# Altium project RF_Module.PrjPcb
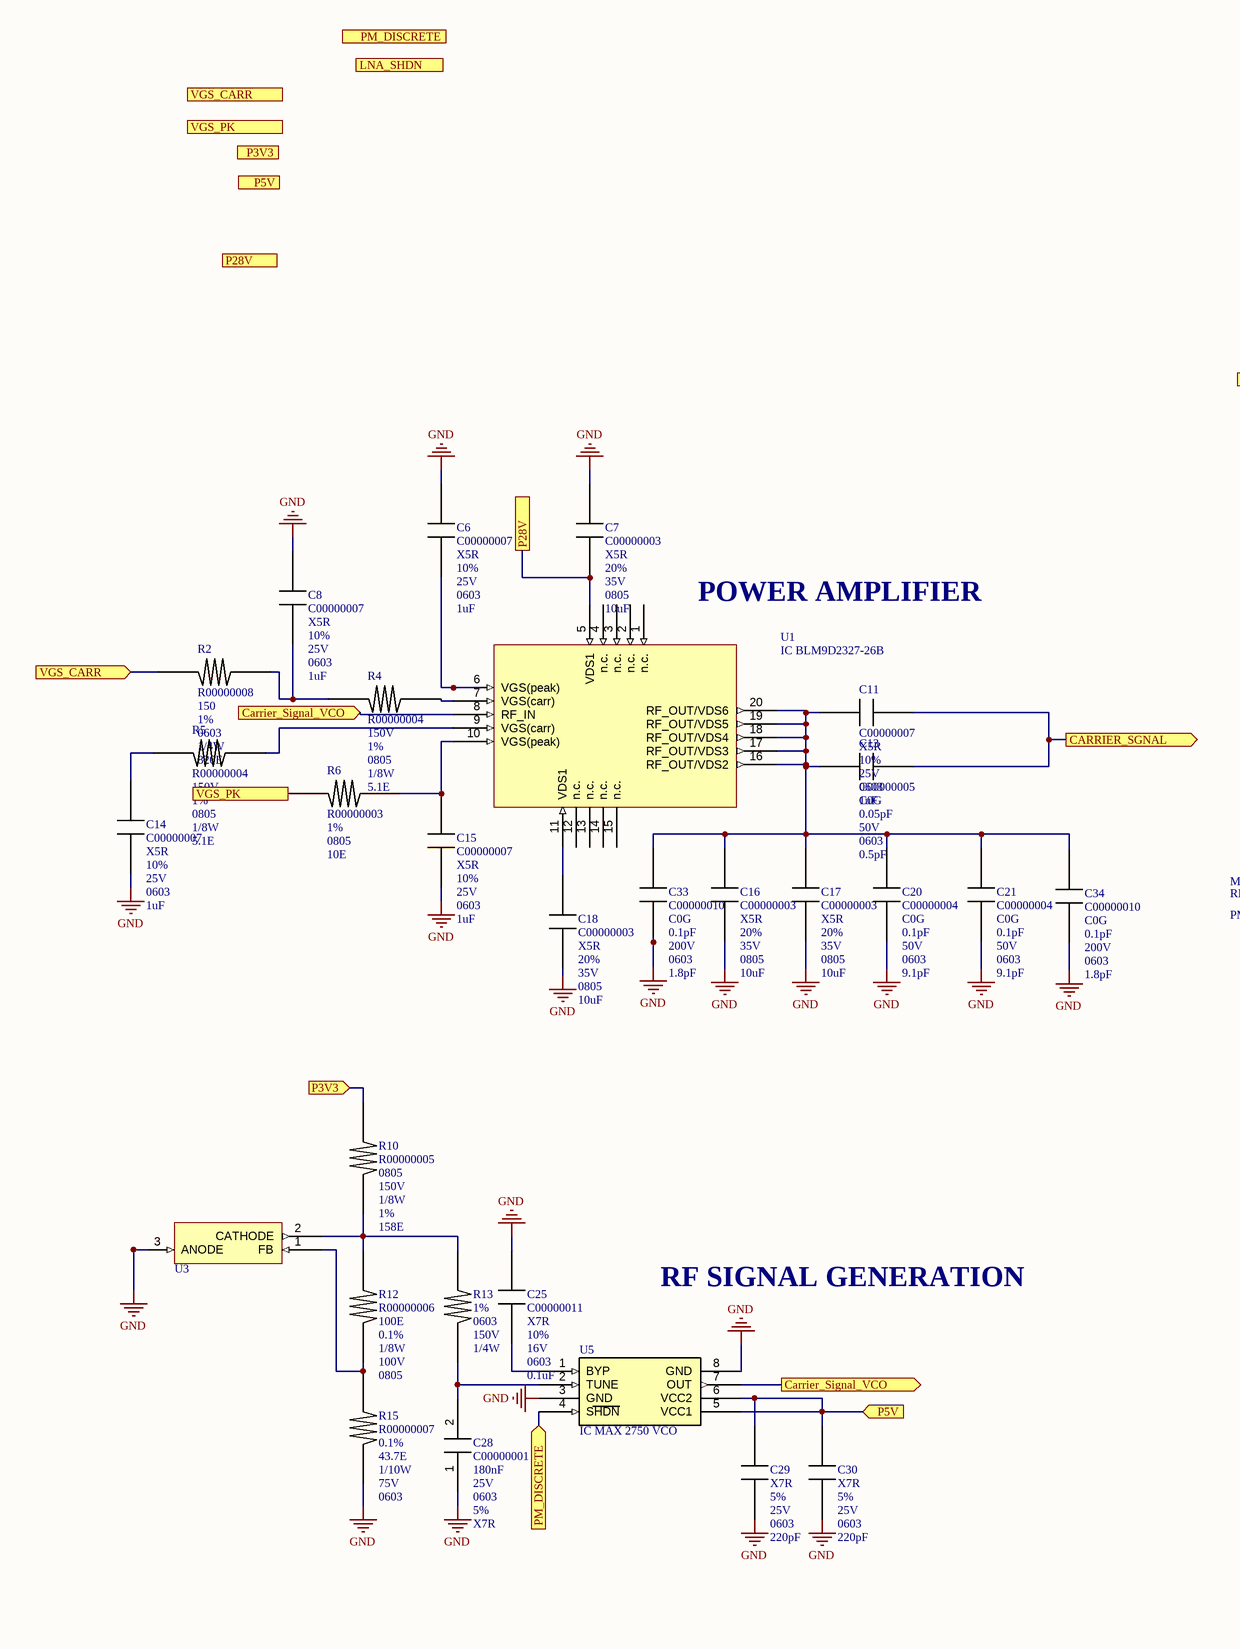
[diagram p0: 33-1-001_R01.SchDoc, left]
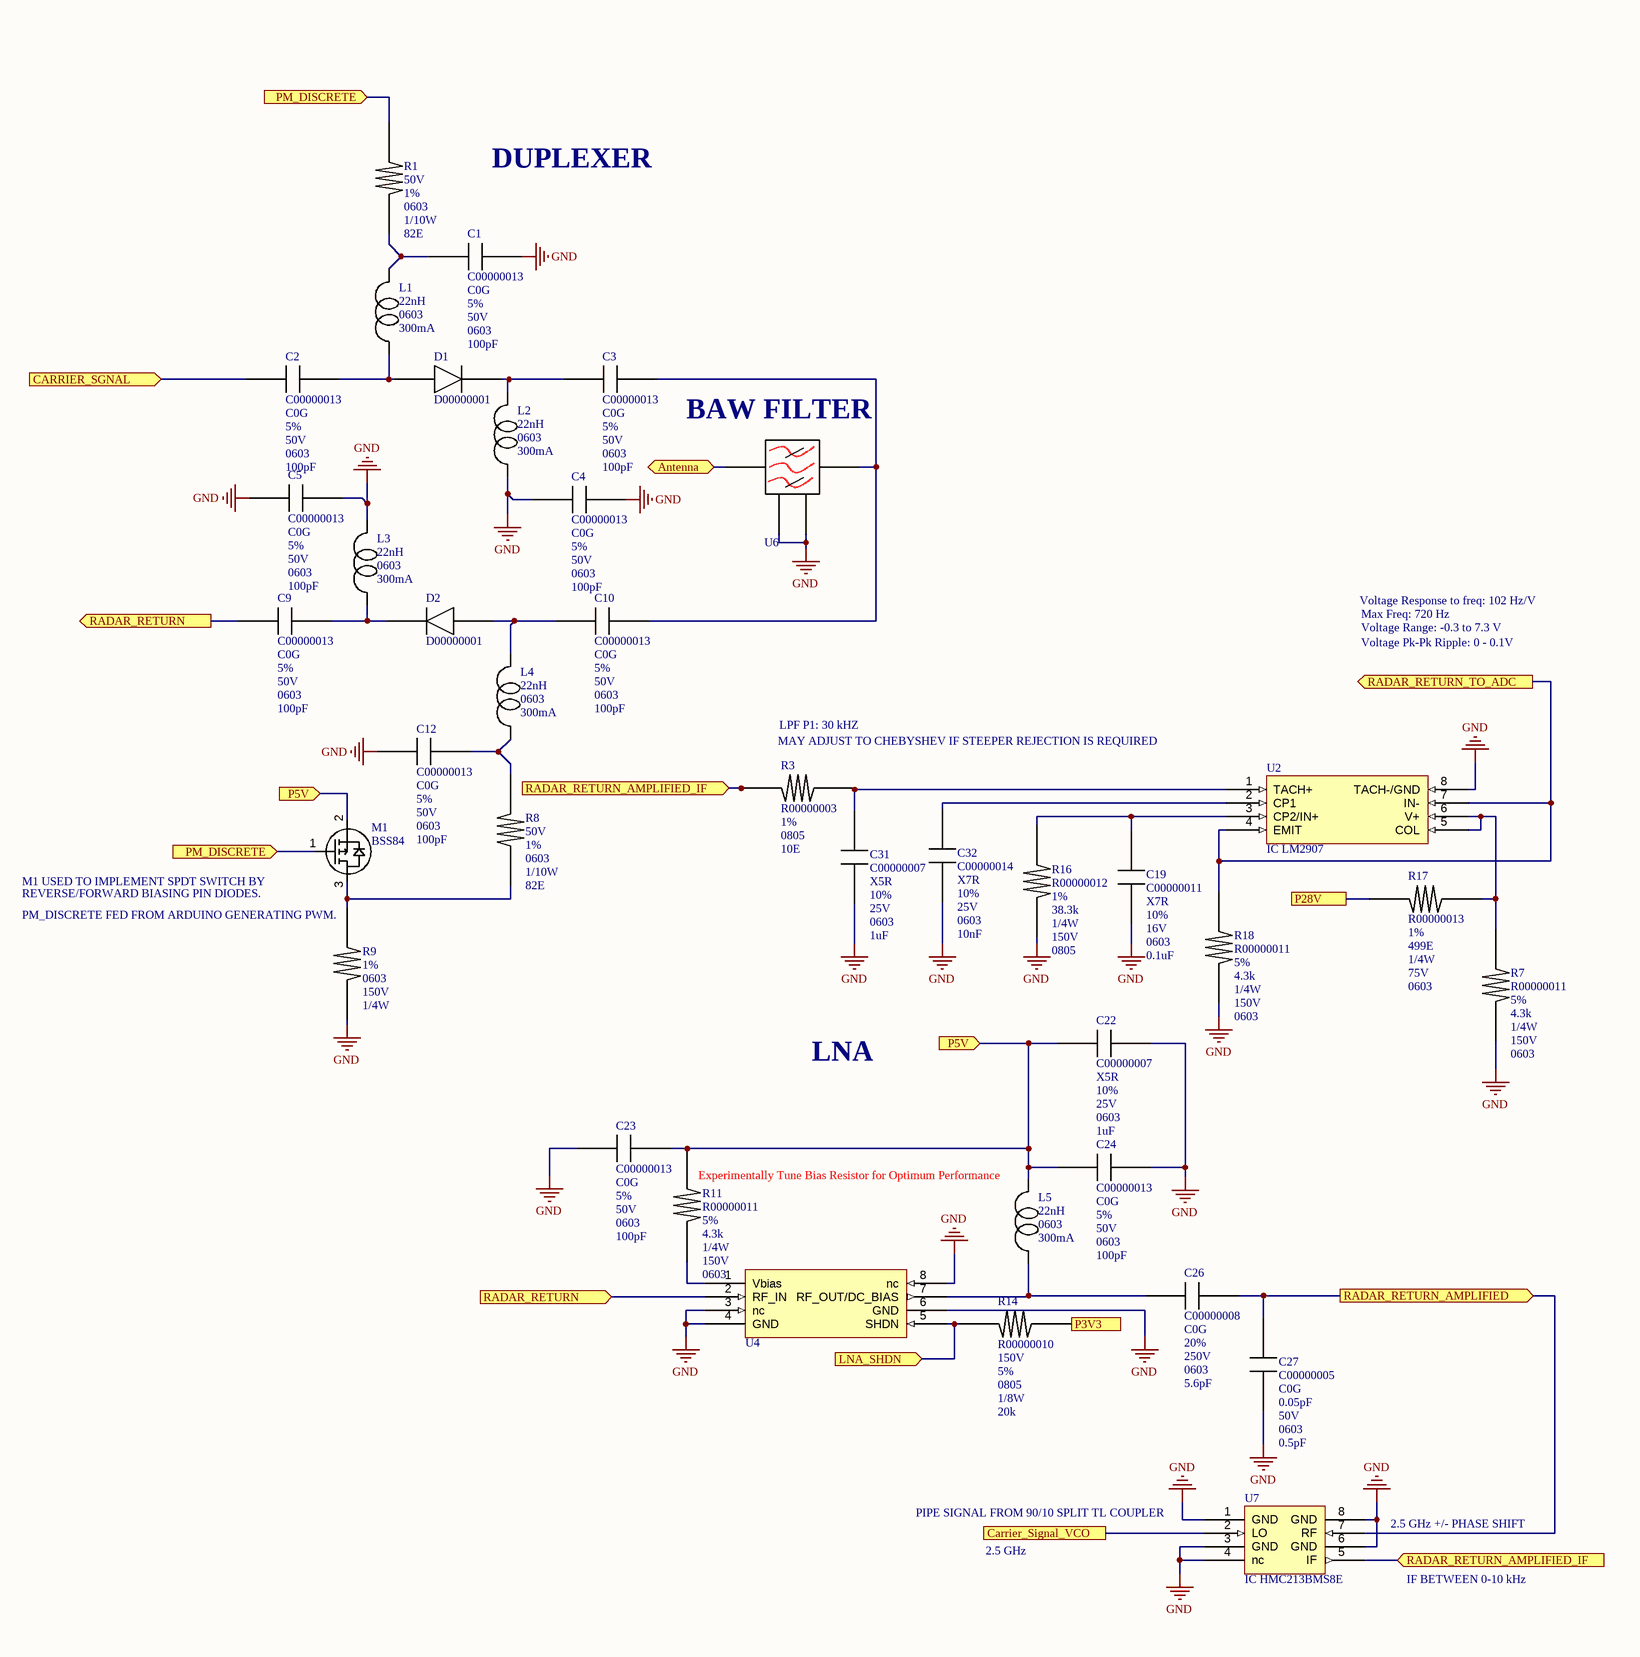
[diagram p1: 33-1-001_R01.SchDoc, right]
1 sheet, 67 parts. Net scope: flat (ports and power ports of the same name join across sheets).
Board file: PCB1.PcbDoc

## Sheet 33-1-001_R01.SchDoc: RF Module
size 558 x 431 mm; Date: 10/26/2021; ApprovedBy: G. Mays; CheckedBy: J. Lusher; Author: G. Mays; CompanyName: Team 33; DrawnBy: G. Mays; Engineer: G. Mays; Organization: Texas A&M; DocumentNumber: 33-1-001; Revision: 01; SheetNumber: 1; SheetTotal: 1

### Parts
C1  C00000013  Dielectric: C0G  Tolerance: 5%  Voltage: 50V  Package: 0603  Capacitance: 100pF  [C0603C101J5GAC7082]
C2  C00000013  Dielectric: C0G  Tolerance: 5%  Voltage: 50V  Package: 0603  Capacitance: 100pF  [C0603C101J5GAC7082]
C3  C00000013  Dielectric: C0G  Tolerance: 5%  Voltage: 50V  Package: 0603  Capacitance: 100pF  [C0603C101J5GAC7082]
C4  C00000013  Dielectric: C0G  Tolerance: 5%  Voltage: 50V  Package: 0603  Capacitance: 100pF  [C0603C101J5GAC7082]
C5  C00000013  Dielectric: C0G  Tolerance: 5%  Voltage: 50V  Package: 0603  Capacitance: 100pF  [C0603C101J5GAC7082]
C6  C00000007  Dielectric: X5R  Tolerance: 10%  Voltage: 25V  Package: 0603  Capacitance: 1uF  [06033D105KAT2A]
C7  C00000003  Dielectric: X5R  Tolerance: 20%  Voltage: 35V  Package: 0805  Capacitance: 10uF  [C2012X5R1V106K125AC]
C8  C00000007  Dielectric: X5R  Tolerance: 10%  Voltage: 25V  Package: 0603  Capacitance: 1uF  [06033D105KAT2A]
C9  C00000013  Dielectric: C0G  Tolerance: 5%  Voltage: 50V  Package: 0603  Capacitance: 100pF  [C0603C101J5GAC7082]
C10  C00000013  Dielectric: C0G  Tolerance: 5%  Voltage: 50V  Package: 0603  Capacitance: 100pF  [C0603C101J5GAC7082]
C11  C00000007  Dielectric: X5R  Tolerance: 10%  Voltage: 25V  Package: 0603  Capacitance: 1uF  [06033D105KAT2A]
C12  C00000013  Dielectric: C0G  Tolerance: 5%  Voltage: 50V  Package: 0603  Capacitance: 100pF  [C0603C101J5GAC7082]
C13  C00000005  Dielectric: C0G  Tolerance: 0.05pF  Voltage: 50V  Package: 0603  Capacitance: 0.5pF  [CBR06C508A5GAC]
C14  C00000007  Dielectric: X5R  Tolerance: 10%  Voltage: 25V  Package: 0603  Capacitance: 1uF  [06033D105KAT2A]
C15  C00000007  Dielectric: X5R  Tolerance: 10%  Voltage: 25V  Package: 0603  Capacitance: 1uF  [06033D105KAT2A]
C16  C00000003  Dielectric: X5R  Tolerance: 20%  Voltage: 35V  Package: 0805  Capacitance: 10uF  [C2012X5R1V106K125AC]
C17  C00000003  Dielectric: X5R  Tolerance: 20%  Voltage: 35V  Package: 0805  Capacitance: 10uF  [C2012X5R1V106K125AC]
C18  C00000003  Dielectric: X5R  Tolerance: 20%  Voltage: 35V  Package: 0805  Capacitance: 10uF  [C2012X5R1V106K125AC]
C19  C00000011  Dielectric: X7R  Tolerance: 10%  Voltage: 16V  Package: 0603  Capacitance: 0.1uF  [C0603C104K4RACTU]
C20  C00000004  Dielectric: C0G  Tolerance: 0.1pF  Voltage: 50V  Package: 0603  Capacitance: 9.1pF  [06035U9R1BAT2A]
C21  C00000004  Dielectric: C0G  Tolerance: 0.1pF  Voltage: 50V  Package: 0603  Capacitance: 9.1pF  [06035U9R1BAT2A]
C22  C00000007  Dielectric: X5R  Tolerance: 10%  Voltage: 25V  Package: 0603  Capacitance: 1uF  [06033D105KAT2A]
C23  C00000013  Dielectric: C0G  Tolerance: 5%  Voltage: 50V  Package: 0603  Capacitance: 100pF  [C0603C101J5GAC7082]
C24  C00000013  Dielectric: C0G  Tolerance: 5%  Voltage: 50V  Package: 0603  Capacitance: 100pF  [C0603C101J5GAC7082]
C25  C00000011  Dielectric: X7R  Tolerance: 10%  Voltage: 16V  Package: 0603  Capacitance: 0.1uF  [C0603C104K4RACTU]
C26  C00000008  Dielectric: C0G  Tolerance: 20%  Voltage: 250V  Package: 0603  Capacitance: 5.6pF  [GQM1875C2E1R6BB12D]
C27  C00000005  Dielectric: C0G  Tolerance: 0.05pF  Voltage: 50V  Package: 0603  Capacitance: 0.5pF  [CBR06C508A5GAC]
C28  C00000001  Capacitance: 180nF  Voltage: 25V  Package: 0603  Tolerance: 5%  Dielectric: X7R  [C0603C184J3RACTU]
C29  Dielectric: X7R  Tolerance: 5%  Voltage: 25V  Package: 0603  Capacitance: 220pF  [C0603C221J3RACAUTO]  (hidden comment: C00000012)
C30  Dielectric: X7R  Tolerance: 5%  Voltage: 25V  Package: 0603  Capacitance: 220pF  [C0603C221J3RACAUTO]  (hidden comment: C00000012)
C31  C00000007  Dielectric: X5R  Tolerance: 10%  Voltage: 25V  Package: 0603  Capacitance: 1uF  [06033D105KAT2A]
C32  C00000014  Dielectric: X7R  Tolerance: 10%  Voltage: 25V  Package: 0603  Capacitance: 10nF  [AC0603KRX7R8BB103]
C33  C00000010  Dielectric: C0G  Tolerance: 0.1pF  Voltage: 200V  Package: 0603  Capacitance: 1.8pF  [VJ0603D1R8BXCQJHT]
C34  C00000010  Dielectric: C0G  Tolerance: 0.1pF  Voltage: 200V  Package: 0603  Capacitance: 1.8pF  [VJ0603D1R8BXCQJHT]
D1  D00000001  [SMP1334-084LF]
D2  D00000001  [SMP1334-084LF]
L1  Inductance: 22nH  Package: 0603  Imax: 300mA  [ILC0603ER22NJ]  (hidden comment: L00000001)
L2  Inductance: 22nH  Package: 0603  Imax: 300mA  [ILC0603ER22NJ]  (hidden comment: L00000001)
L3  Inductance: 22nH  Package: 0603  Imax: 300mA  [ILC0603ER22NJ]  (hidden comment: L00000001)
L4  Inductance: 22nH  Package: 0603  Imax: 300mA  [ILC0603ER22NJ]  (hidden comment: L00000001)
L5  Inductance: 22nH  Package: 0603  Imax: 300mA  [ILC0603ER22NJ]  (hidden comment: L00000001)
M1  BSS84  [BSS84,215]
R1  Voltage Rating: 50V  Tolerance: 1%  Package: 0603  Power: 1/10W  Resistance: 82E  [CR0603-JW-820ELF]  (hidden comment: R00000009)
R2  R00000008  Voltage Rating: 150  Tolerance: 1%  Package: 0603  Power: 1/4W  Resistance: 820E  [ERJ-U3RD8200V]
R3  R00000003  Tolerance: 1%  Package: 0805  Resistance: 10E  [SFR10EZPF10R0]
R4  R00000004  Voltage Rating: 150V  Tolerance: 1%  Package: 0805  Power: 1/8W  Resistance: 5.1E  [CRCW08055R10FKTA]
R5  R00000004  Voltage Rating: 150V  Tolerance: 1%  Package: 0805  Power: 1/8W  Resistance: 5.1E  [CRCW08055R10FKTA]
R6  R00000003  Tolerance: 1%  Package: 0805  Resistance: 10E  [SFR10EZPF10R0]
R7  R00000011  Tolerance: 5%  Resistance: 4.3k  Power: 1/4W  Voltage Rating: 150V  Package: 0603  [ESR03EZPJ432]
R8  Voltage Rating: 50V  Tolerance: 1%  Package: 0603  Power: 1/10W  Resistance: 82E  [CR0603-JW-820ELF]  (hidden comment: R00000009)
R9  Tolerance: 1%  Package: 0603  Voltage Rating: 150V  Power: 1/4W  [ERJ-UP3F8660V]  (hidden comment: R00000001)
R10  R00000005  Package: 0805  Voltage Rating: 150V  Power: 1/8W  Tolerance: 1%  Resistance: 158E  [CR0805-FX-1580ELF]
R11  R00000011  Tolerance: 5%  Resistance: 4.3k  Power: 1/4W  Voltage Rating: 150V  Package: 0603  [ESR03EZPJ432]
R12  R00000006  Resistance: 100E  Tolerance: 0.1%  Power: 1/8W  Voltage Rating: 100V  Package: 0805  [ERA-6AEB101V]
R13  Tolerance: 1%  Package: 0603  Voltage Rating: 150V  Power: 1/4W  [ERJ-UP3F8660V]  (hidden comment: R00000001)
R14  R00000010  Voltage Rating: 150V  Tolerance: 5%  Package: 0805  Power: 1/8W  Resistance: 20k  [CR0805-JW-203ELF]
R15  R00000007  Tolerance: 0.1%  Resistance: 43.7E  Power: 1/10W  Voltage Rating: 75V  Package: 0603  [RN73H1JTTD43R7B25 - duplicate]
R16  R00000012  Tolerance: 1%  Resistance: 38.3k  Power: 1/4W  Voltage Rating: 150V  Package: 0805  [RK73H2ATTD3832F]
R17  R00000013  Tolerance: 1%  Resistance: 499E  Power: 1/4W  Voltage Rating: 75V  Package: 0603  [RCS0603499RFKEA]
R18  R00000011  Tolerance: 5%  Resistance: 4.3k  Power: 1/4W  Voltage Rating: 150V  Package: 0603  [ESR03EZPJ432]
U1  IC BLM9D2327-26B  [BLM9D2327-26B]
U2  IC LM2907  [LM2907]
U3  IC TL4051AQDBZR  [TL4051AQDBZR]  (value not drawn)
U4  IC QPL9503  [QPL9503]  (value not drawn)
U5  IC MAX 2750 VCO  [MAX2750EUA+]
U6  DEA162495BT-1289A1  [DEA162495BT-1289A1]  (value not drawn)
U7  IC HMC213BMS8E  [HMC213BMS8E]

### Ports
Antenna (bidir), CARRIER_SGNAL (in), CARRIER_SGNAL (out), Carrier_Signal_VCO, Carrier_Signal_VCO (in), Carrier_Signal_VCO (out), LNA_SHDN (in), P3V3 (in), P5V (in), P28V, PM_DISCRETE (in), RADAR_RETURN (in), RADAR_RETURN (out), RADAR_RETURN_AMPLIFIED (out), RADAR_RETURN_AMPLIFIED_IF (in), RADAR_RETURN_TO_ADC (out), VGS_CARR (in), VGS_PK (in)

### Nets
GND: C1.2 C4.1 C4.2 C5.1 C5.2 C6.2 C7.2 C8.2 C12.2 C14.1 C15.1 C16.1 C17.1 C18.1 C19.1 C20.1 C21.1 C22.1 C23.1 C24.2 C25.2 C27.1 C28.1 C29.1 C30.1 C31.1 C32.1 C33.1 C34.1 L2.1 L3.2 R7.1 R9.1 R15.1 R16.1 R18.1 U2.8(TACH-/GND) U3.3(ANODE) U4.3(nc) U4.4(GND) U4.6(GND) U4.8(nc) U5.3(GND) U5.8(GND) U6.2 U6.4 U7.1(GND) U7.3(GND) U7.4(nc) U7.6(GND) U7.8(GND)
NetC1_1: C1.1 L1.2 R1.1
NetC2_1: C2.1 C11.1 C13.2 ; port CARRIER_SGNAL
NetC2_2: C2.2 D1.2 L1.1
NetC3_1: C3.1 D1.1 L2.2
NetC3_2: C3.2 C10.2 U6.3
NetC6_1: C6.1 U1.6(VGS(peak))
NetC7_1: C7.1 R17.1 U1.5(VDS1) ; port P28V
NetC8_1: C8.1 R2.2 R4.1
NetC9_1: C9.1 U4.2(RF_IN) ; port RADAR_RETURN
NetC9_2: C9.2 D2.1 L3.1
NetC10_1: C10.1 D2.2 L4.2
NetC11_2: C11.2 C13.1 C16.2 C17.2 C20.2 C21.2 C33.2 C34.2 U1.16(RF_OUT/VDS2) U1.17(RF_OUT/VDS3) U1.18(RF_OUT/VDS4) U1.19(RF_OUT/VDS5) U1.20(RF_OUT/VDS6)
NetC12_1: C12.1 L4.1 R8.1
NetC14_2: C14.2 R5.1
NetC15_2: C15.2 R6.2 U1.10(VGS(peak))
NetC18_2: C18.2 U1.11(VDS1)
NetC19_2: C19.2 R16.2 U2.3(CP2/IN+)
NetC22_2: C22.2 C23.2 C24.1 C29.2 C30.2 L5.2 M1.2 R11.2 U5.5(VCC1) U5.6(VCC2) ; port P5V
NetC25_1: C25.1 U5.1(BYP)
NetC26_1: C26.1 L5.1 U4.7(RF_OUT/DC_BIAS)
NetC26_2: C26.2 C27.2 U7.7(RF) ; port RADAR_RETURN_AMPLIFIED
NetC28_2: C28.2 R13.1 U5.2(TUNE)
NetC31_2: C31.2 R3.2 U2.1(TACH+)
NetC32_2: C32.2 U2.2(CP1)
NetM1_1: M1.1 R1.2 U5.4(SHDN) ; port PM_DISCRETE
NetM1_3: M1.3 R8.2 R9.2
NetR2_1: R2.1 ; port VGS_CARR
NetR3_1: R3.1 U7.5(IF) ; port RADAR_RETURN_AMPLIFIED_IF
NetR4_2: R4.2 U1.7(VGS(carr))
NetR5_2: R5.2 U1.9(VGS(carr))
NetR6_1: R6.1 ; port VGS_PK
NetR7_2: R7.2 R17.2 U2.5(COL) U2.6(V+)
NetR10_1: R10.1 R12.2 R13.2 U3.2(CATHODE)
NetR10_2: R10.2 R14.2 ; port P3V3
NetR11_1: R11.1 U4.1(Vbias)
NetR12_1: R12.1 R15.2 U3.1(FB)
NetR14_1: R14.1 U4.5(SHDN) ; port LNA_SHDN
NetR18_2: R18.2 U2.4(EMIT) U2.7(IN-) ; port RADAR_RETURN_TO_ADC
NetU1_8: U1.8(RF_IN) U5.7(OUT) U7.2(LO) ; port Carrier_Signal_VCO
NetU6_1: U6.1 ; port Antenna

Not connected (* = marked no-connect by the designer): U1 1(n.c.) 2(n.c.) 3(n.c.) 4(n.c.) 12(n.c.) 13(n.c.) 14(n.c.) 15(n.c.)

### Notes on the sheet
- DUPLEXER
- (near U6) BAW FILTER
- (near U1) POWER AMPLIFIER
- Voltage Response to freq: 102 Hz/V
- Max Freq: 720 Hz
- Voltage Range: -0.3 to 7.3 V
- Voltage Pk-Pk Ripple: 0 - 0.1V
- LPF P1: 30 kHZ
- (near R3) MAY ADJUST TO CHEBYSHEV IF STEEPER REJECTION IS REQUIRED
- M1 USED TO IMPLEMENT SPDT SWITCH BY
- REVERSE/FORWARD BIASING PIN DIODES.
- PM_DISCRETE FED FROM ARDUINO GENERATING PWM.
- LNA
- Experimentally Tune Bias Resistor for Optimum Performance
- RF SIGNAL GENERATION
- PIPE SIGNAL FROM 90/10 SPLIT TL COUPLER
- 2.5 GHz +/- PHASE SHIFT
- 2.5 GHz
- IF BETWEEN 0-10 kHz

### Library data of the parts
C1-C5 C9 C10 C12 C23 C24 = C00000013: MLCC 100pF 5% 50V 0603
C6 C8 C11 C14 C15 C22 C31 = C00000007: MLCC 1uF 25V X5R 0603
C7 C16-C18 = C00000003: MLCC 10uF 35V X5R 0805
C13 C27 = C00000005: MLCC 0.5pF 50V 0603 C0G
C19 C25 = C00000011: MLCC 0.1uF 16V 0603 X7R
C20 C21 = C00000004: MLCC 9.1pF 50V 0603 C0G
C26 = C00000008: MLCC 5.6pF 250V C0G 0603
C28 = C00000001: MLCC 180nF 25V X7R 0603
C29 C30 = C00000012: MLCC 220pF 5% 25V 0603 X7R
C32 = C00000014: MLCC 10nF 25V 10% 0603 X7R
C33 C34 = C00000010: MLCC 1.8 pF 250V C0G 0603
D1 D2 = D00000001: PIN DIODE .45 Pf .45 OHM .37 nH, 1-8GHz, SMP1334-084LF
L1-L5 = L00000001: 22nH 300mA 0603 RF Inductor
M1 = BSS84: MOSFET P-CH DMOS 50V 130MA
R1 R8 = R00000009: RES CHIP 82E 5% 1/10W
R2 = R00000008: RES CHIP 820E 1%
R3 R6 = R00000003: RES CHIP 10E 0805 1%
R4 R5 = R00000004: RES CHIP 5.1E 0805 1%
R7 R11 R18 = R00000011: RES CHIP 4.3k 5% 0603 ESR03EZPJ432
R9 R13 = R00000001: RES CHIP 866 0603 1%; Resistance: 866E
R10 = R00000005: RES CHIP 158E 0805 1%
R12 = R00000006: RES CHIP 100E 0.1%
R14 = R00000010: RES CHIP 20k 5% / CR0805-JW-203ELF
R15 = R00000007: RES CHIP 43.7E 0603 0.1%
R16 = R00000012: RES CHIP 38.3k 1% 0805
R17 = R00000013: RES CHIP 499E 1% 0603 75V
U1 = IC BLM9D2327-26B: LDMOS 2-stage integrated Doherty MMIC
U3 = IC TL4051AQDBZR: Precision voltage reference
U5 = IC MAX 2750 VCO: 2.4-2.5 GHz VCO
U6 = DEA162495BT-1289A1: 2.5GHz BPF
